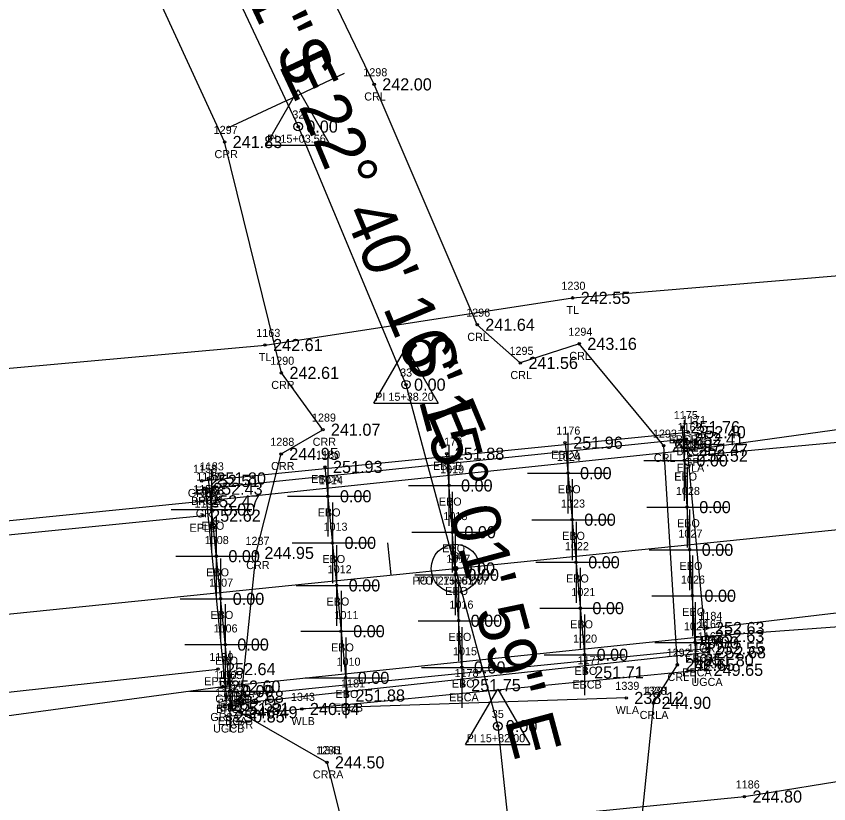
# Model space of a CAD drawing. Extents: x 2274993 to 2278766, y 1075634 to 1076749.
# Drawn here: x 2276295.7 to 2276396.4, y 1076041.3 to 1076138.8 of the extents above; entities that cross this region are included whole.
import ezdxf

# ---------------------------------------------------------------- set-up
doc = ezdxf.new("R2010")
doc.units = 0
for name, color, linetype in [('RD_EX_Bridge', 7, 'Continuous'), ('RD_EX_Bridge_txCode', 7, 'Continuous'), ('RD_EX_GuardRail', 7, 'Continuous'), ('RD_EX_GuardRail_txCode', 7, 'Continuous'), ('RD_EX_H2O', 7, 'Continuous'), ('RD_EX_H2O_txCode', 7, 'Continuous'), ('RD_EX_Road', 7, 'Continuous'), ('RD_EX_Road_txCode', 7, 'Continuous'), ('RD_EX_TX_Bridge_ELEV', 7, 'Continuous'), ('RD_EX_TX_GuardRail_ELEV', 7, 'Continuous'), ('RD_EX_TX_H2O_ELEV', 7, 'Continuous'), ('RD_EX_TX_Road_ELEV', 7, 'Continuous'), ('RD_EX_TX_UT_ELEV', 7, 'Continuous'), ('RD_EX_TX_VEG_ELEV', 7, 'Continuous'), ('RD_EX_UT', 7, 'Continuous'), ('RD_EX_UT_txCode', 7, 'Continuous'), ('RD_EX_VEG', 7, 'Continuous'), ('RD_EX_VEG_txCode', 7, 'Continuous'), ('RD_HC_Cl', 7, 'Continuous'), ('RD_HC_Data', 7, 'Continuous'), ('RD_HC_Data_Tic', 7, 'Continuous'), ('RD_HC_Survey_ELEV', 7, 'Continuous'), ('RD_HC_txCode', 7, 'Continuous'), ('RD_SMD_Locator', 7, 'Continuous')]:
    doc.layers.add(name, color=color, linetype=linetype)

msp = doc.modelspace()

# ---------------------------------------------------------------- linework, layer by layer
at = {"layer": 'RD_EX_Bridge'}
for p, q in [((2276379.94, 1076059.05), (2276378.23, 1076087.92)), ((2276378.47, 1076088.81), (2276378.47, 1076078.81)), ((2276364.06, 1076087.23), (2276364.06, 1076077.23)), ((2276363.71, 1076086), (2276366.31, 1076057.54)), ((2276349.32, 1076085.7), (2276349.32, 1076075.7)), ((2276334.32, 1076084.36), (2276334.32, 1076074.36)), ((2276351.08, 1076055.96), (2276349.04, 1076084.63)), ((2276333.96, 1076083), (2276336.74, 1076054.68)), ((2276373.47, 1076083.81), (2276383.47, 1076083.81)), ((2276378.82, 1076083.02), (2276378.82, 1076073.02)), ((2276319.91, 1076082.71), (2276319.91, 1076072.71)), ((2276359.06, 1076082.23), (2276369.06, 1076082.23)), ((2276322.42, 1076053.03), (2276319.52, 1076081.57)), ((2276364.58, 1076081.46), (2276364.58, 1076071.46)), ((2276344.32, 1076080.7), (2276354.32, 1076080.7)), ((2276349.73, 1076079.91), (2276349.73, 1076069.91)), ((2276329.32, 1076079.36), (2276339.32, 1076079.36)), ((2276334.89, 1076078.59), (2276334.89, 1076068.59)), ((2276373.82, 1076078.02), (2276383.82, 1076078.02)), ((2276314.91, 1076077.71), (2276324.91, 1076077.71)), ((2276320.5, 1076076.94), (2276320.5, 1076066.94)), ((2276379.13, 1076077.73), (2276379.13, 1076067.73)), ((2276359.58, 1076076.46), (2276369.58, 1076076.46)), ((2276365.07, 1076076.18), (2276365.07, 1076066.18)), ((2276344.73, 1076074.91), (2276354.73, 1076074.91)), ((2276350.11, 1076074.63), (2276350.11, 1076064.63)), ((2276329.89, 1076073.59), (2276339.89, 1076073.59)), ((2276335.4, 1076073.32), (2276335.4, 1076063.32)), ((2276315.5, 1076071.94), (2276325.5, 1076071.94)), ((2276374.13, 1076072.73), (2276384.13, 1076072.73)), ((2276379.47, 1076072.04), (2276379.47, 1076062.04)), ((2276321.04, 1076071.66), (2276321.04, 1076061.66)), ((2276360.07, 1076071.18), (2276370.07, 1076071.18)), ((2276365.59, 1076070.5), (2276365.59, 1076060.5)), ((2276345.11, 1076069.63), (2276355.11, 1076069.63)), ((2276350.51, 1076068.94), (2276350.51, 1076058.94)), ((2276330.4, 1076068.32), (2276340.4, 1076068.32)), ((2276335.96, 1076067.64), (2276335.96, 1076057.64)), ((2276374.47, 1076067.04), (2276384.47, 1076067.04)), ((2276316.04, 1076066.66), (2276326.04, 1076066.66)), ((2276321.61, 1076065.99), (2276321.61, 1076055.99)), ((2276379.81, 1076066.25), (2276379.81, 1076056.25)), ((2276360.59, 1076065.5), (2276370.59, 1076065.5)), ((2276345.51, 1076063.94), (2276355.51, 1076063.94)), ((2276366.11, 1076064.73), (2276366.11, 1076054.73)), ((2276350.92, 1076063.16), (2276350.92, 1076053.16)), ((2276330.96, 1076062.64), (2276340.96, 1076062.64)), ((2276336.53, 1076061.87), (2276336.53, 1076051.87)), ((2276316.61, 1076060.99), (2276326.61, 1076060.99)), ((2276374.81, 1076061.25), (2276384.81, 1076061.25)), ((2276322.2, 1076060.22), (2276322.2, 1076050.22)), ((2276361.11, 1076059.73), (2276371.11, 1076059.73)), ((2276345.92, 1076058.16), (2276355.92, 1076058.16)), ((2276331.53, 1076056.87), (2276341.53, 1076056.87)), ((2276317.2, 1076055.22), (2276327.2, 1076055.22))]:
    msp.add_line(p, q, dxfattribs=at)
msp.add_lwpolyline([(2276319.11, 1076080.29), (2276321.74, 1076054.53), (2276381.23, 1076060.52), (2276378.73, 1076086.44), (2276319.11, 1076080.29)], dxfattribs=at)
at = {"layer": 'RD_EX_GuardRail'}
for p, q in [((2276318.7, 1076081.27), (2276378.95, 1076087.3)), ((2276321.49, 1076053.52), (2276381.45, 1076060.04))]:
    msp.add_line(p, q, dxfattribs=at)
for points in [[(2276235.72, 1076070.41), (2276318.74, 1076078.74), (2276379.22, 1076085.12), (2276462.21, 1076096.64)], [(2276238.11, 1076044.54), (2276321.32, 1076055.79), (2276381.25, 1076062.04), (2276465.67, 1076068.19)]]:
    msp.add_lwpolyline(points, dxfattribs=at)
at = {"layer": 'RD_EX_H2O'}
for points in [[(2276374.66, 1076053.77), (2276377.62, 1076058.48), (2276375.93, 1076085.62), (2276365.46, 1076098.25), (2276358.16, 1076095.88), (2276352.82, 1076100.61), (2276340.06, 1076130.39), (2276314.72, 1076182.94), (2276314.31, 1076195.95), (2276321.34, 1076195.98), (2276333.33, 1076184.02), (2276355.21, 1076176.64), (2276375.26, 1076196.07), (2276380, 1076232.36), (2276383.62, 1076239.24), (2276390.64, 1076244.46), (2276451.84, 1076220.12), (2276472.79, 1076219.91), (2276480.77, 1076232.08), (2276477.11, 1076285.34), (2276453.42, 1076310.35), (2276458.35, 1076317.97), (2276489.24, 1076360.6), (2276498.15, 1076406.79)], [(2276334.2, 1076046.4), (2276323.43, 1076052.59), (2276325.46, 1076072.34), (2276328.54, 1076084.61), (2276333.7, 1076087.61), (2276328.57, 1076094.65), (2276321.53, 1076123.25), (2276297.42, 1076175.68), (2276298.22, 1076215.44)], [(2276374.66, 1076053.77), (2276373.09, 1076038.49), (2276378.35, 1076001.85), (2276379.41, 1075939.56), (2276393.18, 1075928.69), (2276410.52, 1075916.05), (2276439.66, 1075905.97), (2276458.4, 1075912.38), (2276470.74, 1075911.86), (2276484.27, 1075900.43), (2276472.97, 1075846.67), (2276473.8, 1075804.25), (2276499.15, 1075757.95), (2276529.69, 1075749.92)], [(2276334.2, 1076046.4), (2276337.42, 1076033.52), (2276345.85, 1076017.42), (2276339.02, 1075984.54), (2276329.97, 1075967.39)]]:
    msp.add_lwpolyline(points, dxfattribs=at)
at = {"layer": 'RD_EX_Road'}
for points in [[(2276379.21, 1076084.39), (2276432.25, 1076089.28), (2276486.22, 1076095.98), (2276535.61, 1076103.32), (2276577.16, 1076110.11), (2276620.86, 1076117.78), (2276666.21, 1076126.9), (2276712, 1076137.22), (2276761.13, 1076149.72), (2276804.56, 1076161.71), (2276851.24, 1076175.53), (2276896.93, 1076190.53), (2276950.19, 1076208.22), (2276997.45, 1076224.3), (2277053.81, 1076243.77), (2277132.14, 1076270.77)], [(2276381.27, 1076063.04), (2276433.15, 1076069.16), (2276488.59, 1076076.23), (2276537.45, 1076083.34), (2276579.64, 1076090.09), (2276624.07, 1076098.24), (2276670.54, 1076107.46), (2276716.67, 1076118.09), (2276765.18, 1076130.28), (2276809.58, 1076142.25), (2276856.93, 1076156.58), (2276903.53, 1076171.63), (2276957.27, 1076189.46), (2277005.85, 1076206.01), (2277060.98, 1076225.07), (2277139.5, 1076252.36)], [(2275577.73, 1075970.55), (2275625.95, 1075985.49), (2275674.01, 1075998.04), (2275722.5, 1076008.98), (2275771.65, 1076017.82), (2275820.48, 1076025.1), (2275865.7, 1076030.61), (2275949.17, 1076039.36), (2275965.19, 1076041.07), (2276054.28, 1076050.49), (2276149.42, 1076060.39), (2276235.13, 1076068.68), (2276318.87, 1076076.96)], [(2275583.24, 1075951.04), (2275629.66, 1075965.93), (2275678.06, 1075978.68), (2275725.56, 1075989.06), (2275775.66, 1075998.23), (2275820.79, 1076005.15), (2275867.87, 1076010.76), (2275970.82, 1076021.78), (2276056.64, 1076030.61), (2276150.8, 1076040.39), (2276237.04, 1076048.76), (2276320.71, 1076057.95)]]:
    msp.add_lwpolyline(points, dxfattribs=at)
at = {"layer": 'RD_EX_UT'}
for p, q in [((2276381.1, 1076057.86), (2276321.84, 1076052.09)), ((2276371.28, 1076054.38), (2276331.1, 1076053.01))]:
    msp.add_line(p, q, dxfattribs=at)
at = {"layer": 'RD_EX_VEG'}
for points in [[(2276059.59, 1076114.41), (2276109.62, 1076078.55), (2276326.54, 1076098.1), (2276364.64, 1076103.94), (2276468.17, 1076112.63), (2276687.38, 1076155.02), (2276867.98, 1076201.61), (2276854.55, 1076228.93)], [(2275588.01, 1075931.75), (2275680.64, 1075961.35), (2275730.55, 1075971.06), (2275824.32, 1075986.29), (2275869.68, 1075991.08), (2276385.92, 1076042.16), (2276665.98, 1076087.69), (2276721.29, 1076100.17), (2276841.99, 1076132.87), (2276855.5, 1076106.15)]]:
    msp.add_lwpolyline(points, dxfattribs=at)
at = {"layer": 'RD_HC_Cl'}
for p, q in [((2276305.65, 1076178.38), (2276330.65, 1076125.16)), ((2276305.65, 1076178.38), (2276330.65, 1076125.16)), ((2276330.65, 1076125.16), (2276344, 1076093.19)), ((2276330.65, 1076125.16), (2276344, 1076093.19)), ((2276344, 1076093.19), (2276355.37, 1076050.89)), ((2276344, 1076093.19), (2276355.37, 1076050.89)), ((2275853.33, 1076019.72), (2276414.6, 1076077)), ((2276355.37, 1076050.89), (2276368.02, 1075931.61)), ((2276355.37, 1076050.89), (2276368.02, 1075931.61))]:
    msp.add_line(p, q, dxfattribs=at)
at = {"layer": 'RD_HC_Data'}
for p, q in [((2276326.68, 1076122.86), (2276330.65, 1076129.74)), ((2276330.65, 1076129.74), (2276334.62, 1076122.86)), ((2276326.68, 1076122.86), (2276334.62, 1076122.86)), ((2276340.03, 1076090.9), (2276344.01, 1076097.78)), ((2276344.01, 1076097.78), (2276347.97, 1076090.9)), ((2276340.03, 1076090.9), (2276347.97, 1076090.9)), ((2276351.39, 1076048.6), (2276355.37, 1076055.48)), ((2276355.37, 1076055.48), (2276359.33, 1076048.6)), ((2276351.39, 1076048.6), (2276359.33, 1076048.6))]:
    msp.add_line(p, q, dxfattribs=at)
for centre, radius in [((2276330.65, 1076125.16), 0.529), ((2276344, 1076093.19), 0.529), ((2276350.12, 1076070.42), 3), ((2276350.12, 1076070.42), 3), ((2276350.12, 1076070.42), 0.282), ((2276350.12, 1076070.42), 0.282), ((2276355.37, 1076050.89), 0.529)]:
    msp.add_circle(centre, radius, dxfattribs=at)
at = {"layer": 'RD_HC_Data_Tic'}
for p, q in [((2276329.14, 1076128.37), (2276336.38, 1076131.78)), ((2276329.14, 1076128.37), (2276321.9, 1076124.97)), ((2276342.16, 1076069.61), (2276341.75, 1076073.59))]:
    msp.add_line(p, q, dxfattribs=at)
at = {"layer": 'RD_SMD_Locator'}
for centre in [(2276340.06, 1076130.39), (2276330.65, 1076125.16), (2276321.53, 1076123.25), (2276364.64, 1076103.94), (2276352.82, 1076100.61), (2276326.54, 1076098.1), (2276365.46, 1076098.25), (2276358.16, 1076095.88), (2276328.57, 1076094.65), (2276344, 1076093.19), (2276378.23, 1076087.92), (2276333.7, 1076087.61), (2276378.95, 1076087.3), (2276363.71, 1076086), (2276378.73, 1076086.44), (2276375.93, 1076085.62), (2276379.22, 1076085.12), (2276328.54, 1076084.61), (2276349.04, 1076084.63), (2276378.47, 1076083.81), (2276379.21, 1076084.39), (2276333.96, 1076083), (2276364.06, 1076082.23), (2276318.7, 1076081.27), (2276319.52, 1076081.57), (2276319.11, 1076080.29), (2276319.11, 1076080.29), (2276349.32, 1076080.7), (2276318.74, 1076078.74), (2276334.32, 1076079.36), (2276319.91, 1076077.71), (2276378.82, 1076078.02), (2276318.87, 1076076.96), (2276364.58, 1076076.46), (2276349.73, 1076074.91), (2276334.89, 1076073.59), (2276379.13, 1076072.73), (2276320.5, 1076071.94), (2276325.46, 1076072.34), (2276365.07, 1076071.18), (2276350.12, 1076070.42), (2276350.12, 1076070.42), (2276350.11, 1076069.63), (2276335.4, 1076068.32), (2276321.04, 1076066.66), (2276379.47, 1076067.04), (2276365.59, 1076065.5), (2276350.51, 1076063.94), (2276335.96, 1076062.64), (2276381.27, 1076063.04), (2276381.25, 1076062.04), (2276321.61, 1076060.99), (2276379.81, 1076061.25), (2276366.11, 1076059.73), (2276381.23, 1076060.52), (2276381.45, 1076060.04), (2276379.94, 1076059.05), (2276320.71, 1076057.95), (2276350.92, 1076058.16), (2276377.62, 1076058.48), (2276381.1, 1076057.86), (2276336.53, 1076056.87), (2276366.31, 1076057.54), (2276321.32, 1076055.79), (2276351.08, 1076055.96), (2276322.2, 1076055.22), (2276336.74, 1076054.68), (2276321.74, 1076054.53), (2276371.28, 1076054.38), (2276374.66, 1076053.77), (2276374.66, 1076053.77), (2276321.49, 1076053.52), (2276322.42, 1076053.03), (2276323.43, 1076052.59), (2276331.1, 1076053.01), (2276321.84, 1076052.09), (2276355.37, 1076050.89), (2276334.2, 1076046.4), (2276334.2, 1076046.4), (2276385.92, 1076042.16)]:
    msp.add_circle(centre, 0.15, dxfattribs=at)

# ---------------------------------------------------------------- texts
at = {"layer": 'RD_EX_Bridge_txCode'}
for s, p in [('1175', (2276377.17, 1076088.92)), ('1176', (2276362.62, 1076087)), ('1169', (2276377.64, 1076087.44)), ('EBCB', (2276376.53, 1076085.92)), ('1179', (2276347.98, 1076085.63)), ('1029', (2276377.09, 1076085.31)), ('1180', (2276332.86, 1076084)), ('EBCA', (2276361.99, 1076084)), ('BRC', (2276377.48, 1076084.44)), ('1024', (2276362.67, 1076083.73)), ('1183', (2276318.46, 1076082.57)), ('EBCB', (2276347.34, 1076082.63)), ('1019', (2276348.22, 1076082.2)), ('1170', (2276318.01, 1076081.29)), ('1157', (2276318.05, 1076081.29)), ('EBCA', (2276332.25, 1076081)), ('1014', (2276333.22, 1076080.86)), ('EBO', (2276377.23, 1076081.31)), ('EBCB', (2276317.82, 1076079.57)), ('1009', (2276318.49, 1076079.21)), ('EBO', (2276362.81, 1076079.73)), ('1028', (2276377.43, 1076079.52)), ('BRCA', (2276317.37, 1076078.29)), ('BRCB', (2276317.39, 1076078.29)), ('EBO', (2276348.07, 1076078.2)), ('1023', (2276363.2, 1076077.96)), ('EBO', (2276333.07, 1076076.86)), ('1018', (2276348.63, 1076076.41)), ('EBO', (2276318.67, 1076075.21)), ('1013', (2276333.78, 1076075.09)), ('EBO', (2276377.57, 1076075.52)), ('EBO', (2276363.34, 1076073.96)), ('1027', (2276377.74, 1076074.23)), ('1008', (2276319.07, 1076073.44)), ('EBO', (2276348.49, 1076072.41)), ('1022', (2276363.68, 1076072.68)), ('EBO', (2276333.64, 1076071.09)), ('1017', (2276349, 1076071.13)), ('1012', (2276334.3, 1076069.82)), ('EBO', (2276377.89, 1076070.23)), ('EBO', (2276319.26, 1076069.44)), ('1007', (2276319.61, 1076068.16)), ('EBO', (2276363.82, 1076068.68)), ('1026', (2276378.06, 1076068.54)), ('EBO', (2276348.86, 1076067.13)), ('1021', (2276364.48, 1076067)), ('EBO', (2276334.16, 1076065.82)), ('1016', (2276349.38, 1076065.44)), ('EBO', (2276319.79, 1076064.16)), ('1011', (2276335.14, 1076064.14)), ('EBO', (2276378.22, 1076064.54)), ('EBO', (2276364.34, 1076063)), ('1025', (2276378.42, 1076062.75)), ('1006', (2276320.16, 1076062.49)), ('EBO', (2276349.27, 1076061.44)), ('1020', (2276364.69, 1076061.23)), ('1165', (2276380.14, 1076061.52)), ('EBO', (2276334.72, 1076060.14)), ('1174', (2276378.88, 1076060.05)), ('1015', (2276349.82, 1076059.66)), ('EBO', (2276378.57, 1076058.75)), ('EBO', (2276320.37, 1076058.49)), ('1010', (2276335.39, 1076058.37)), ('1177', (2276365.25, 1076058.54)), ('BRC', (2276379.98, 1076058.52)), ('1005', (2276320.77, 1076056.72)), ('1178', (2276350.01, 1076056.96)), ('EBO', (2276364.87, 1076057.23)), ('EBCA', (2276378.22, 1076057.05)), ('1164', (2276320.66, 1076055.53)), ('1181', (2276335.96, 1076055.68)), ('EBO', (2276349.68, 1076055.66)), ('EBCB', (2276364.61, 1076055.54)), ('1182', (2276321.36, 1076054.03)), ('EBO', (2276335.28, 1076054.37)), ('EBCA', (2276349.36, 1076053.96)), ('EBO', (2276320.95, 1076052.72)), ('EBCB', (2276335.04, 1076052.68)), ('BRC', (2276320.49, 1076052.53)), ('EBCA', (2276320.7, 1076051.03))]:
    msp.add_text(s, height=1, dxfattribs=at).set_placement(p)
at = {"layer": 'RD_EX_GuardRail_txCode'}
for s, p in [('1171', (2276378.17, 1076088.3)), ('1172', (2276378.16, 1076086.12)), ('GR2B', (2276377.25, 1076085.3)), ('GR', (2276378.44, 1076083.12)), ('1158', (2276317.63, 1076082.27)), ('GR2A', (2276316.98, 1076079.27)), ('1156', (2276317.66, 1076079.74)), ('GR', (2276317.97, 1076076.74)), ('1167', (2276380.16, 1076063.04)), ('1166', (2276380.34, 1076061.04)), ('GR1', (2276380.3, 1076060.04)), ('GR3B', (2276379.75, 1076058.04)), ('1162', (2276320.24, 1076056.79)), ('GR1', (2276320.38, 1076053.79)), ('1160', (2276320.36, 1076054.52)), ('GR3A', (2276319.77, 1076051.52))]:
    msp.add_text(s, height=1, dxfattribs=at).set_placement(p)
at = {"layer": 'RD_EX_H2O_txCode'}
for s, p in [('1298', (2276338.71, 1076131.39)), ('CRL', (2276338.83, 1076128.39)), ('1297', (2276320.18, 1076124.25)), ('CRR', (2276320.28, 1076121.25)), ('1296', (2276351.45, 1076101.61)), ('1294', (2276364.11, 1076099.25)), ('CRL', (2276351.59, 1076098.61)), ('1295', (2276356.82, 1076096.88)), ('CRL', (2276364.23, 1076096.25)), ('1290', (2276327.18, 1076095.65)), ('CRL', (2276356.93, 1076093.88)), ('CRR', (2276327.31, 1076092.65)), ('1289', (2276332.35, 1076088.61)), ('1293', (2276374.58, 1076086.62)), ('1288', (2276327.19, 1076085.61)), ('CRR', (2276332.44, 1076085.61)), ('CRL', (2276374.7, 1076083.62)), ('CRR', (2276327.29, 1076082.61)), ('1287', (2276324.12, 1076073.34)), ('CRR', (2276324.21, 1076070.34)), ('1292', (2276376.28, 1076059.48)), ('CRL', (2276376.39, 1076056.48)), ('1338', (2276373.31, 1076054.77)), ('1291', (2276373.59, 1076054.77)), ('1286', (2276322.06, 1076053.59)), ('CRLA', (2276372.94, 1076051.77)), ('CRLA', (2276372.94, 1076051.77)), ('CRR', (2276322.17, 1076050.59)), ('1285', (2276332.86, 1076047.4)), ('1341', (2276333.14, 1076047.4)), ('CRRA', (2276332.46, 1076044.4)), ('CRRA', (2276332.46, 1076044.4))]:
    msp.add_text(s, height=1, dxfattribs=at).set_placement(p)
at = {"layer": 'RD_EX_Road_txCode'}
for s, p in [('1185', (2276378.15, 1076085.39)), ('EPLA', (2276377.52, 1076082.39)), ('1155', (2276317.8, 1076077.96)), ('EPLB', (2276317.19, 1076074.96)), ('1184', (2276380.21, 1076064.04)), ('EPRA', (2276379.55, 1076061.04)), ('1159', (2276319.65, 1076058.95)), ('EPRB', (2276319.01, 1076055.95))]:
    msp.add_text(s, height=1, dxfattribs=at).set_placement(p)
at = {"layer": 'RD_EX_TX_Bridge_ELEV'}
for s, p in [('251.76', (2276379.23, 1076087.17)), ('252.41', (2276379.73, 1076085.69)), ('251.96', (2276364.71, 1076085.25)), ('251.88', (2276350.04, 1076083.88)), ('0.00', (2276379.97, 1076083.06)), ('251.93', (2276334.96, 1076082.25)), ('0.00', (2276365.56, 1076081.48)), ('251.80', (2276320.52, 1076080.82)), ('252.43', (2276320.11, 1076079.54)), ('252.43', (2276320.11, 1076079.54)), ('0.00', (2276350.82, 1076079.95)), ('0.00', (2276335.82, 1076078.61)), ('0.00', (2276321.41, 1076076.96)), ('0.00', (2276380.32, 1076077.27)), ('0.00', (2276366.08, 1076075.71)), ('0.00', (2276351.23, 1076074.16)), ('0.00', (2276336.39, 1076072.84)), ('0.00', (2276380.63, 1076071.98)), ('0.00', (2276322, 1076071.19)), ('0.00', (2276366.57, 1076070.43)), ('0.00', (2276351.61, 1076068.88)), ('0.00', (2276336.9, 1076067.57)), ('0.00', (2276380.97, 1076066.29)), ('0.00', (2276322.54, 1076065.91)), ('0.00', (2276367.09, 1076064.75)), ('0.00', (2276352.01, 1076063.19)), ('0.00', (2276337.46, 1076061.89)), ('0.00', (2276323.11, 1076060.24)), ('0.00', (2276381.31, 1076060.5)), ('252.55', (2276382.23, 1076059.77)), ('0.00', (2276367.61, 1076058.98)), ('251.80', (2276380.94, 1076058.3)), ('0.00', (2276352.42, 1076057.41)), ('251.71', (2276367.31, 1076056.79)), ('0.00', (2276338.03, 1076056.12)), ('251.75', (2276352.08, 1076055.21)), ('0.00', (2276323.7, 1076054.47)), ('252.68', (2276322.74, 1076053.78)), ('251.88', (2276337.74, 1076053.93)), ('251.81', (2276323.42, 1076052.28))]:
    msp.add_text(s, height=1.5, dxfattribs=at).set_placement(p)
at = {"layer": 'RD_EX_TX_GuardRail_ELEV'}
for s, p in [('252.40', (2276379.95, 1076086.55)), ('252.47', (2276380.22, 1076084.37)), ('252.51', (2276319.7, 1076080.52)), ('252.47', (2276319.74, 1076077.99)), ('252.63', (2276382.25, 1076061.29)), ('252.68', (2276382.45, 1076059.29)), ('252.60', (2276322.32, 1076055.04)), ('252.55', (2276322.49, 1076052.77))]:
    msp.add_text(s, height=1.5, dxfattribs=at).set_placement(p)
at = {"layer": 'RD_EX_TX_H2O_ELEV'}
for s, p in [('242.00', (2276341.06, 1076129.64)), ('241.83', (2276322.53, 1076122.5)), ('241.64', (2276353.82, 1076099.86)), ('243.16', (2276366.46, 1076097.5)), ('241.56', (2276359.16, 1076095.13)), ('242.61', (2276329.57, 1076093.9)), ('241.07', (2276334.7, 1076086.86)), ('241.97', (2276376.93, 1076084.87)), ('244.95', (2276329.54, 1076083.86)), ('244.95', (2276326.46, 1076071.59)), ('242.65', (2276378.62, 1076057.73)), ('244.90', (2276375.66, 1076053.02)), ('244.90', (2276375.66, 1076053.02)), ('246.49', (2276324.43, 1076051.84)), ('244.50', (2276335.2, 1076045.65)), ('244.50', (2276335.2, 1076045.65))]:
    msp.add_text(s, height=1.5, dxfattribs=at).set_placement(p)
at = {"layer": 'RD_EX_TX_Road_ELEV'}
for s, p in [('252.52', (2276380.21, 1076083.64)), ('252.62', (2276319.87, 1076076.21)), ('252.63', (2276382.27, 1076062.29)), ('252.64', (2276321.71, 1076057.2))]:
    msp.add_text(s, height=1.5, dxfattribs=at).set_placement(p)
at = {"layer": 'RD_EX_TX_UT_ELEV'}
for s, p in [('249.65', (2276382.1, 1076057.11)), ('238.12', (2276372.28, 1076053.63)), ('240.34', (2276332.1, 1076052.26)), ('250.85', (2276322.84, 1076051.34))]:
    msp.add_text(s, height=1.5, dxfattribs=at).set_placement(p)
at = {"layer": 'RD_EX_TX_VEG_ELEV'}
for s, p in [('242.55', (2276365.64, 1076103.19)), ('242.61', (2276327.54, 1076097.35)), ('244.80', (2276386.92, 1076041.41))]:
    msp.add_text(s, height=1.5, dxfattribs=at).set_placement(p)
at = {"layer": 'RD_EX_UT_txCode'}
for s, p in [('1337', (2276379.76, 1076058.86)), ('UGCA', (2276379.35, 1076055.86)), ('1339', (2276369.93, 1076055.38)), ('1343', (2276329.75, 1076054.01)), ('1340', (2276320.46, 1076053.09)), ('WLA', (2276369.97, 1076052.38)), ('WLB', (2276329.81, 1076051.01)), ('UGCB', (2276320.11, 1076050.09))]:
    msp.add_text(s, height=1, dxfattribs=at).set_placement(p)
at = {"layer": 'RD_EX_VEG_txCode'}
for s, p in [('1230', (2276363.25, 1076104.94)), ('TL', (2276363.87, 1076101.94)), ('1163', (2276325.46, 1076099.1)), ('TL', (2276325.77, 1076096.1)), ('1186', (2276384.84, 1076043.16))]:
    msp.add_text(s, height=1, dxfattribs=at).set_placement(p)
at = {"layer": 'RD_HC_Data'}
for s, rotation, p in [('S 25%%d 09\' 41" E', 295.1614, (2276307.47, 1076176.85)), ('S 25%%d 09\' 41" E', 295.1614, (2276307.47, 1076176.85)), ('S 22%%d 40\' 16" E', 292.671, (2276327.75, 1076134.7)), ('S 22%%d 40\' 16" E', 292.671, (2276327.75, 1076134.7)), ('S 15%%d 01\' 59" E', 285.0331, (2276343.58, 1076098.61)), ('S 15%%d 01\' 59" E', 285.0331, (2276343.58, 1076098.61))]:
    msp.add_text(s, height=6, rotation=rotation, dxfattribs=at).set_placement(p)
at = {"layer": 'RD_HC_Survey_ELEV'}
for p in [(2276331.65, 1076124.41), (2276345, 1076092.44), (2276351.12, 1076069.67), (2276351.12, 1076069.67), (2276356.37, 1076050.14)]:
    msp.add_text('0.00', height=1.5, dxfattribs=at).set_placement(p)
at = {"layer": 'RD_HC_txCode'}
for s, p in [('32', (2276329.92, 1076126.16)), ('PI 15+03.56', (2276326.81, 1076123.16)), ('33', (2276343.27, 1076094.19)), ('PI 15+38.20', (2276340.19, 1076091.19)), ('34', (2276349.39, 1076071.42)), ('9', (2276349.84, 1076071.42)), ('POT 27+08.00', (2276344.8, 1076068.42)), ('POT 15+61.77', (2276345.47, 1076068.42)), ('35', (2276354.63, 1076051.89)), ('PI 15+82.00', (2276351.51, 1076048.89))]:
    msp.add_text(s, height=1, dxfattribs=at).set_placement(p)

doc.saveas('drawing.dxf')
